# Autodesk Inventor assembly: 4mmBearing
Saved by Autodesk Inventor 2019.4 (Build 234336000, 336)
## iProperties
Created: 2020-02
Part Number: 4mmBearing
Document SubType Name: Assembly
Designer: Administrator
Title: 4mmBearing v4
Author: Administrator
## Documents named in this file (2)
- c:\worker\convert-fusion-r01\tmp\job-1\5\output\files\e4333473-a38b-4431-9958-ad24a2f67704\4mmBearing v4_1.iam
- c:\worker\convert-fusion-r01\tmp\job-1\5\output\files\e4333473-a38b-4431-9958-ad24a2f67704\4mmBearing.ipt
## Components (1 placed, 1 different names)
1. 4mmBearing:1
